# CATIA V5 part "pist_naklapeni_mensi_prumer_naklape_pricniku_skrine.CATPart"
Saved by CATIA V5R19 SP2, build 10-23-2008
Part number: pist_naklapeni_mensi_prumer_naklape_pricniku_skrine
Bounding box of the stored display mesh (mm): x -50 to 50, y -55 to 55, z 0 to 395
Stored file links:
  D:\Catia fórum\Modely - Otazky\Naklapeni_oprava\pist_naklapeni_mensi_prumer_naklape_pricniku_skrine.CATPart
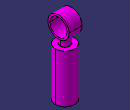
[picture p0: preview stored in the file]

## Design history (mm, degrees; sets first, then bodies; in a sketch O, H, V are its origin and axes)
Body1 (main body)
  Sketch1 on xy-plane, origin (0, 0, 0), H (1, 0, 0), V (0, 1, 0)
    circle A1 centre (0, 0) radius 50
    radius A1 = 50
  Pad1: profile Sketch1, direction (0, 0, 1), length 250
  Sketch2 on yz-plane, origin (0, 0, 0), H (0, 1, 0), V (0, 0, 1)
    circle A1 centre (0, 340) radius 45
    point P1 (0, 340)
    circle A2 centre (0, 340) radius 55
    reference projected line E1 (-35, 250) -> (35, 250) from edge [face of Pad1 from Sketch1.A1 | end face of Pad1]
    distance P1 E1 = 90
    radius A2 = 55
    radius A1 = 45
    coincidence: P1 V
    concentricity: A2 A1
  Pad2: profile Sketch2, direction (1, 0, 0), length 34, mirrored extent
  Sketch3 on end face of Pad1, origin (0, 0, 250), H (1, 0, 0), V (0, 1, 0)
    circle A1 centre (0, 0) radius 25
    radius A1 = 25
  Pad3: profile Sketch3, direction (0, 0, 1), up to the existing solid (limit type 2)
